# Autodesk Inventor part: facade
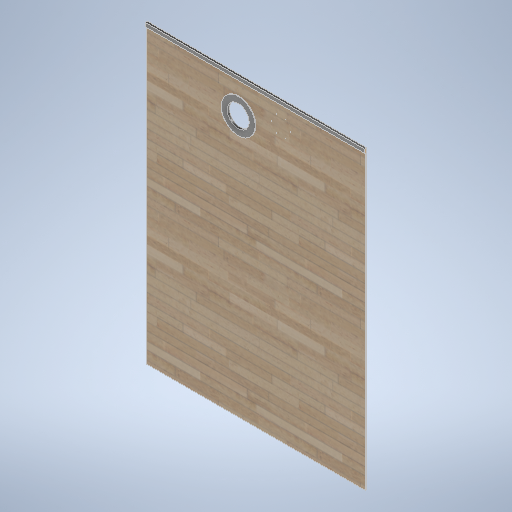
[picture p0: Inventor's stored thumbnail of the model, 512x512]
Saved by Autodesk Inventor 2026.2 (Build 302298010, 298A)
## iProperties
Created: 2026-09
Part Number: facade
Material: Bois (Erable)
Document SubType Name: Modeling
Designer: mel
Density: 0.67 g/cm^3
Appearance: Erable naturel - Lustré teinte foncée
Author: mel
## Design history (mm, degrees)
sketch "Esquisse1"
  geometry: L1 (0, 0)-(-1500, 0); L2 (-1500, 0)-(-1500, -2000); L3 (-1500, -2000)-(0, -2000); L4 (0, -2000)-(0, 0); C1 r 75 at (-865, -212); C2 r 117 at (-865, -212)
  constraints: 8 end point, 2 centre point, 2 parallel, 1 coincident, 1 horizontal, 1 perpendicular
  dimensions: "d0" = 1500 distance between parallel lines of L4 L2; "d1" = 150 diameter of C1; "d3" = 865 distance from line of C1.centre L4 (computed from d1); "d4" = 2000 distance between parallel lines of L1 L3; "d5" = 234 diameter of C2; "d8" = 212 distance from line of L1 C1.centre
extrude "Extrusion1" new body sketch "Esquisse1" distance "d9" = 10; taper "d10" = 0 deg
sketch "Esquisse2"
  geometry: C1 r 75 at (-865, -212) reference; C2 r 117 at (-865, -212); 1 further point
  constraints: 1 centre point, 1 coincident
  dimensions: "d11" = 234 diameter of C2
extrude "Extrusion2" join sketch "Esquisse2" distance "d12" = 4; taper "d13" = 0 deg
sketch "Esquisse3"
  geometry: L1 (0, 2000)-(-15, 2000); L2 (-15, 2000)-(-15, 2025); L3 (-15, 2025)-(0, 2025); L4 (0, 2025)-(0, 2000)
  constraints: 8 end point, 2 parallel, 1 horizontal, 1 perpendicular
  dimensions: "d14" = 15 distance of L2.end L3.end; "d15" = 25 distance of L1.end L2.end
extrude "Extrusion3" join sketch "Esquisse3" stored distance "d16" = 4; taper "d17" = 0 deg
sketch "Esquisse4"
  geometry: L1 (-865, -212)-(-576.113, -131.103); L2 (-576.113, -131.103)-(-520.584, -329.401); C1 r 117 at (-865, -212) reference; C2 r 117 at (-495.216, -419.99); C3 r 75 at (-865, -212) reference; A1 r 300 centre (-576.113, -131.103) between (-865, -212) and (-495.216, -419.99); 7 further points
  constraints: 4 end point, 2 centre point, 2 point on circle, 1 perpendicular, 1 point on line, 7 other
  dimensions: "d18" = 234 diameter of C2; "d19" = 300 distance of L1.start L1.end; "d20" = 65 distance of point (-511.113, -131.103) L1.end; "d30" = 360 deg dimension on L1.end point (-511.113, -131.103) (derived)
hole "Perçage1" sketch "Esquisse4" at (-511.113, -131.103), (-543.613, -74.812), (-608.613, -74.812), (-641.113, -131.103), (-608.613, -187.395), (-543.613, -187.395) diameter "d21" = 4; stored, may be unused: countersink angle "d25" = 90 deg, drill point angle "d27" = 118 deg; dims "d22" = 6, "d23" = 6, "d24" = 2, "d26" = 8
node "Solide1"
node "Réseau d'esquisse circulaire1" dims "d30" = 360 deg (derived)
